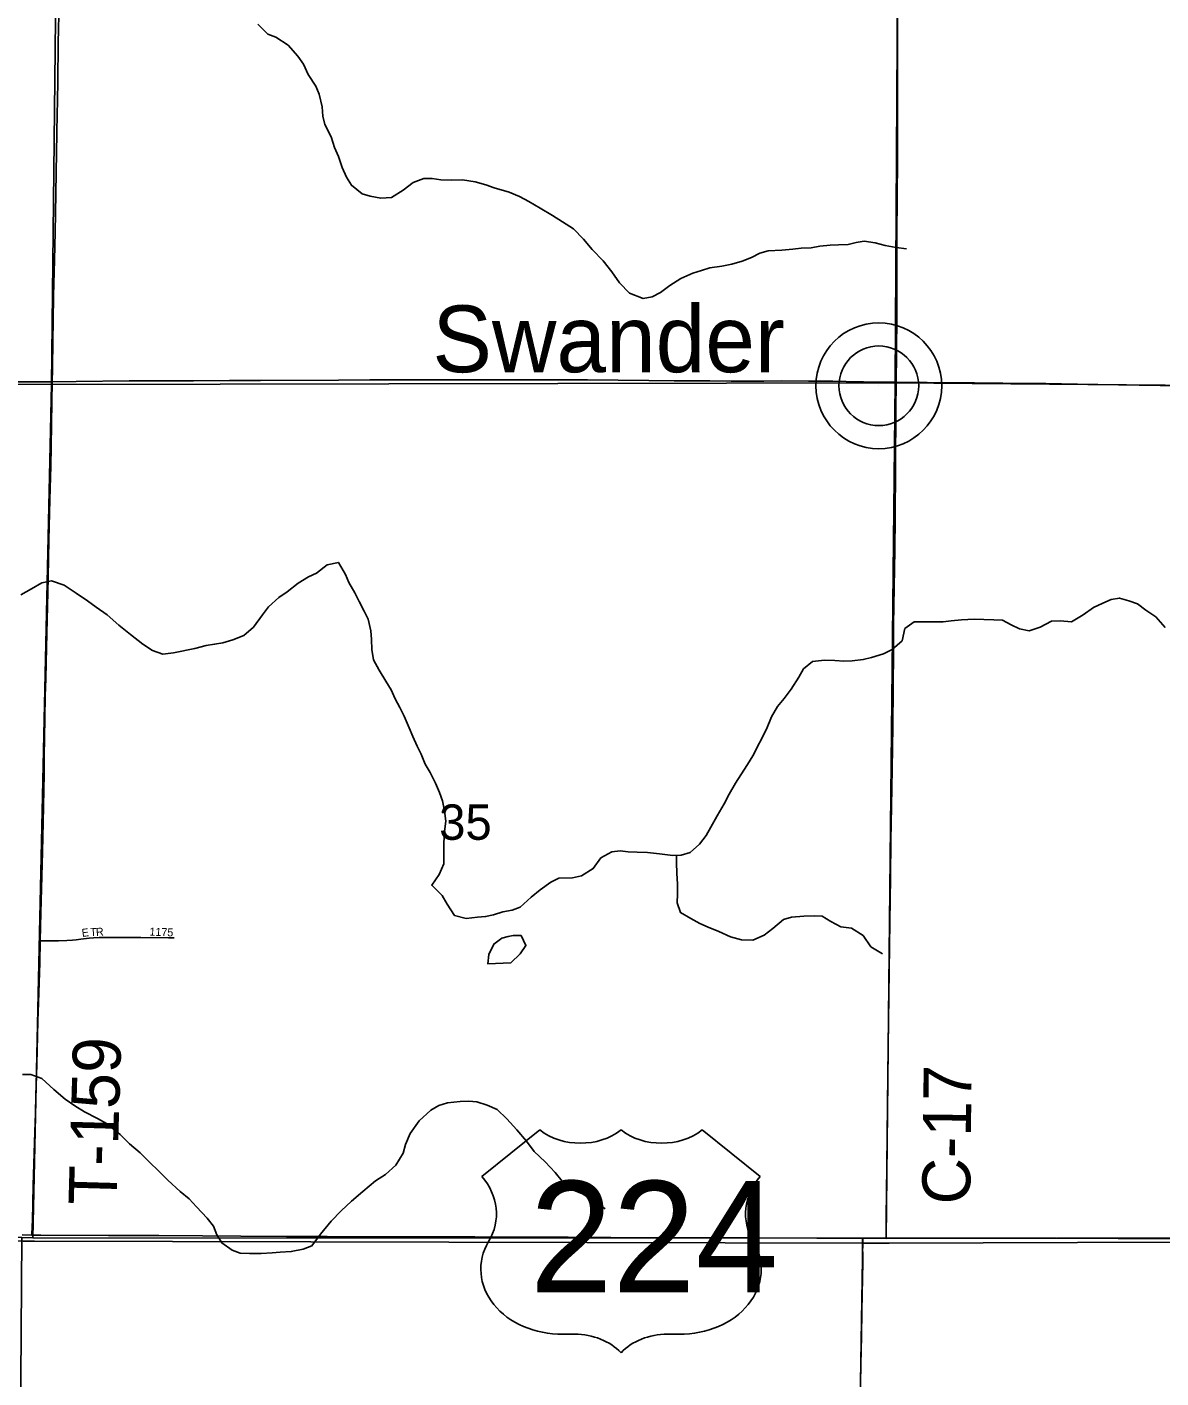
# Model space of a CAD drawing. Extents: x 0 to 34, y 0 to 22.
# Drawn here: x 7.481 to 8.152, y 17.325 to 18.124 of the extents above; entities that cross this region are included whole.
import ezdxf

# ---------------------------------------------------------------- set-up
doc = ezdxf.new("R2010")
doc.units = 0
for name, color, linetype in [('GM_X_County_Road', 7, 'Continuous'), ('GM_X_County_Road_Text', 7, 'Continuous'), ('GM_X_Minor_Lake', 7, 'Continuous'), ('GM_X_Minor_River', 7, 'Continuous'), ('GM_X_Section', 7, 'Continuous'), ('GM_X_Section_Text', 7, 'Continuous'), ('GM_X_Township', 7, 'Continuous'), ('GM_X_Township_Road', 7, 'Continuous'), ('GM_X_Township_Road_Text', 7, 'Continuous'), ('GM_X_Township_Subdivision', 7, 'Continuous'), ('GM_X_Township_Subdivision_Text', 7, 'Continuous'), ('GM_X_Unincorporated', 7, 'Continuous'), ('GM_X_Unincorporated_Location', 7, 'Continuous'), ('GM_X_Unincorporated_Text', 7, 'Continuous'), ('GM_X_US_Location', 7, 'Continuous'), ('GM_X_US_Route', 7, 'Continuous'), ('GM_X_US_Shield', 7, 'Continuous')]:
    doc.layers.add(name, color=color, linetype=linetype)

msp = doc.modelspace()

# ---------------------------------------------------------------- linework, layer by layer
at = {"layer": 'GM_X_County_Road'}
for points in [[(7.99571, 17.91394), (7.99585, 17.93046), (7.99605, 17.95429), (7.99603, 17.97419), (7.99617, 18.00589), (7.99623, 18.01863), (7.99641, 18.05025), (7.99647, 18.0754), (7.99657, 18.12233), (7.99659, 18.13787), (7.99671, 18.16117), (7.99673, 18.17267), (7.99692, 18.19444), (7.99714, 18.23162), (7.99728, 18.2571), (7.99724, 18.28784), (7.99731, 18.30959), (7.99763, 18.34688), (7.99777, 18.36771), (7.9982, 18.40065), (7.99821, 18.41029), (7.9981, 18.41846), (7.99806, 18.41977)], [(7.47422, 17.91413), (7.49131, 17.91417), (7.4964, 17.91419)], [(7.4964, 17.91419), (7.51058, 17.91426), (7.54196, 17.9146), (7.55253, 17.91465), (7.56154, 17.91469), (7.57988, 17.91475), (7.60132, 17.91498), (7.61966, 17.91494), (7.66566, 17.915), (7.68431, 17.91519), (7.71943, 17.91524), (7.73839, 17.91523), (7.76357, 17.91521), (7.78252, 17.91529), (7.79496, 17.91534), (7.81298, 17.91526), (7.84935, 17.91493), (7.86427, 17.91479), (7.8854, 17.91465), (7.89814, 17.91456), (7.9174, 17.91457), (7.92766, 17.91463), (7.94383, 17.91458), (7.95813, 17.91441), (7.96621, 17.91424), (7.97366, 17.91411), (7.97645, 17.91407), (7.98608, 17.91397), (7.99509, 17.91395), (7.99571, 17.91394)], [(7.98986, 17.40743), (7.98986, 17.40832), (7.98981, 17.42062), (7.98995, 17.43365), (7.9903, 17.4678), (7.99055, 17.48674), (7.99104, 17.52059), (7.99121, 17.53581), (7.99155, 17.56564), (7.99186, 17.59455), (7.99226, 17.62095), (7.9926, 17.643), (7.99291, 17.66288), (7.99331, 17.68493), (7.99371, 17.7104), (7.99403, 17.75515), (7.99411, 17.77038), (7.99484, 17.81452), (7.99509, 17.83409), (7.99531, 17.86298), (7.99551, 17.89904), (7.9957, 17.91239), (7.99571, 17.91394)], [(7.99571, 17.91394), (8.01405, 17.91379), (8.04202, 17.9135), (8.0588, 17.91332), (8.08429, 17.91304), (8.10294, 17.91274), (8.12718, 17.91239), (8.16416, 17.9118)]]:
    msp.add_lwpolyline(points, dxfattribs=at)
at = {"layer": 'GM_X_Minor_Lake'}
for points in [[(7.76618, 17.58588), (7.76237, 17.58503), (7.75761, 17.58144), (7.75474, 17.57538), (7.75414, 17.56969), (7.76762, 17.57039)], [(7.76762, 17.57039), (7.77315, 17.57568), (7.77659, 17.5806), (7.77376, 17.5865), (7.76902, 17.58652), (7.76618, 17.58588)]]:
    msp.add_lwpolyline(points, dxfattribs=at)
at = {"layer": 'GM_X_Minor_River'}
for points in [[(7.61793, 18.12575), (7.62398, 18.11984), (7.62871, 18.11811), (7.63591, 18.11334), (7.64176, 18.10686), (7.64497, 18.1021), (7.64779, 18.09583), (7.65232, 18.08897), (7.65438, 18.08422), (7.65606, 18.07681), (7.65642, 18.07131), (7.65773, 18.06637), (7.66149, 18.05914), (7.66336, 18.05268), (7.66581, 18.04735), (7.66787, 18.04089), (7.6705, 18.03519), (7.67352, 18.03043), (7.67976, 18.02528), (7.6845, 18.02393), (7.69076, 18.02277), (7.69702, 18.02312), (7.70406, 18.02746), (7.70996, 18.03199), (7.71624, 18.03443), (7.72117, 18.03441), (7.72629, 18.03363), (7.73256, 18.03341), (7.7392, 18.03357), (7.7466, 18.0324), (7.75285, 18.03067), (7.75778, 18.02894), (7.76669, 18.02624), (7.77275, 18.02375), (7.77843, 18.02088), (7.78506, 18.01687), (7.79244, 18.01247), (7.79831, 18.00884), (7.80475, 18.00464), (7.8108, 17.99854), (7.81589, 17.99244), (7.82232, 17.98578), (7.82742, 17.97911), (7.83194, 17.97264), (7.83799, 17.96654), (7.84595, 17.96347), (7.85127, 17.9644), (7.85621, 17.96703), (7.86173, 17.971), (7.8682, 17.97514), (7.87543, 17.97834), (7.88056, 17.98003), (7.8855, 17.98152), (7.89253, 17.98244), (7.89842, 17.98375), (7.9045, 17.98543), (7.9102, 17.98768), (7.91496, 17.99013), (7.9199, 17.99163), (7.92806, 17.99197), (7.93452, 17.99251), (7.93945, 17.99325), (7.94534, 17.99342), (7.95047, 17.99434), (7.95673, 17.99489), (7.96167, 17.99525), (7.96736, 17.99541), (7.97211, 17.99653), (7.97686, 17.99727), (7.98331, 17.99629), (7.98919, 17.99475), (7.99563, 17.99358), (8.00189, 17.9928)], [(7.65282, 17.80088), (7.6591, 17.80579), (7.66575, 17.80728), (7.66989, 17.80005), (7.67196, 17.7953), (7.67535, 17.78921), (7.67799, 17.78408), (7.681, 17.77837), (7.68326, 17.77362), (7.68494, 17.76678), (7.6853, 17.76165), (7.68546, 17.75577), (7.68639, 17.74969), (7.68978, 17.7436), (7.69373, 17.73695), (7.69694, 17.73181), (7.69919, 17.72649), (7.70202, 17.72135), (7.70465, 17.71621), (7.70747, 17.70937), (7.70973, 17.70424), (7.71236, 17.69853), (7.71462, 17.69378), (7.71706, 17.68789), (7.72008, 17.68294), (7.72309, 17.67666), (7.72553, 17.67115), (7.72722, 17.66621), (7.72852, 17.66032), (7.72926, 17.65424), (7.72847, 17.64798), (7.72806, 17.64115), (7.72801, 17.62901), (7.72533, 17.62257), (7.72094, 17.61632), (7.72717, 17.61022), (7.73, 17.60509), (7.73434, 17.59843), (7.74135, 17.59669), (7.748, 17.59742), (7.75274, 17.59778), (7.75749, 17.59871), (7.763, 17.60059), (7.76851, 17.60151), (7.77326, 17.60339), (7.77974, 17.60925), (7.78507, 17.61359), (7.79136, 17.61812), (7.79611, 17.62037), (7.80427, 17.62072), (7.80959, 17.62183), (7.81644, 17.62617), (7.82102, 17.63241), (7.82749, 17.63599), (7.83243, 17.63654), (7.83717, 17.63595), (7.84249, 17.63593), (7.84856, 17.63571), (7.85558, 17.63492), (7.86354, 17.63394), (7.86848, 17.63411), (7.8738, 17.63561), (7.87933, 17.64052), (7.88333, 17.64562), (7.88601, 17.65055), (7.88984, 17.65736), (7.89385, 17.66437), (7.89691, 17.67024), (7.90073, 17.67667), (7.90379, 17.6816), (7.9078, 17.68765), (7.91086, 17.69276), (7.9189, 17.70867), (7.92196, 17.71587), (7.92541, 17.72193), (7.92941, 17.72684), (7.93361, 17.73233), (7.9382, 17.73933), (7.94088, 17.74426), (7.94621, 17.7486), (7.95323, 17.74952), (7.95931, 17.7493), (7.96481, 17.7489), (7.96974, 17.74907), (7.9762, 17.7498), (7.98114, 17.75092), (7.98817, 17.75317), (7.99331, 17.7558), (7.99921, 17.7609), (8.00076, 17.7681), (8.00628, 17.77207), (8.0133, 17.77204), (8.01862, 17.7722), (8.02355, 17.77218), (8.0283, 17.77273), (8.03438, 17.77328), (8.04178, 17.77363), (8.04766, 17.77341), (8.05354, 17.77339), (8.05867, 17.77317), (8.06378, 17.77031)], [(7.47777, 17.78815), (7.48405, 17.79173), (7.49014, 17.79512), (7.49603, 17.79642), (7.50342, 17.79373), (7.51061, 17.78915), (7.51724, 17.78456), (7.52234, 17.78075), (7.52897, 17.77617), (7.53578, 17.77006), (7.54277, 17.76453), (7.54996, 17.75881), (7.55564, 17.75518), (7.5619, 17.75306), (7.56816, 17.7538), (7.5807, 17.7564), (7.58754, 17.75808), (7.59248, 17.75882), (7.59723, 17.75975), (7.6033, 17.76143), (7.60977, 17.76406), (7.61548, 17.76897), (7.62083, 17.77616), (7.62427, 17.78108), (7.63036, 17.78656), (7.63531, 17.78995), (7.64197, 17.79505), (7.64806, 17.79882), (7.65282, 17.80088)], [(8.06378, 17.77031), (8.0687, 17.76801), (8.07439, 17.76685), (8.08086, 17.76891), (8.08751, 17.77248), (8.09264, 17.77265), (8.09947, 17.77205), (8.10632, 17.7762), (8.11241, 17.78054), (8.11793, 17.78317), (8.12287, 17.78524), (8.12781, 17.78617), (8.1333, 17.78463), (8.13842, 17.78271), (8.14334, 17.77908), (8.1494, 17.77507), (8.15487, 17.76879)], [(7.86575, 17.63402), (7.8658, 17.62957), (7.86597, 17.62349), (7.86632, 17.61685), (7.8663, 17.61116), (7.86608, 17.60585), (7.86815, 17.60014), (7.8742, 17.59651), (7.87951, 17.59364), (7.88443, 17.59154), (7.89068, 17.58885), (7.89769, 17.58579), (7.90414, 17.58405), (7.91097, 17.58383), (7.91763, 17.58684), (7.92277, 17.59062), (7.92905, 17.59609), (7.9338, 17.5974), (7.94102, 17.59794), (7.94709, 17.5981), (7.95184, 17.59789), (7.95714, 17.59483), (7.96301, 17.59158), (7.96927, 17.5908), (7.97608, 17.5866), (7.98061, 17.57994), (7.98761, 17.57573)], [(7.47886, 17.50424), (7.48379, 17.50422), (7.49024, 17.50191), (7.49742, 17.49543), (7.50404, 17.48971), (7.50972, 17.4857), (7.5154, 17.48226), (7.52316, 17.47824), (7.52846, 17.47538), (7.5366, 17.46889), (7.54208, 17.46336), (7.54832, 17.45802), (7.55418, 17.45231), (7.55909, 17.44754), (7.56476, 17.44183), (7.57213, 17.43515), (7.57743, 17.43076), (7.58178, 17.426), (7.58801, 17.41933), (7.59179, 17.41458), (7.59385, 17.40944), (7.59668, 17.40469), (7.60292, 17.4003), (7.60766, 17.39857), (7.61316, 17.39836), (7.62, 17.39833), (7.62645, 17.39887), (7.6312, 17.39923), (7.63784, 17.39958), (7.64487, 17.40088), (7.65, 17.40294), (7.65516, 17.40994), (7.66145, 17.41751), (7.66736, 17.42356), (7.67346, 17.42941), (7.68013, 17.43508), (7.68774, 17.44131), (7.69364, 17.44508), (7.69974, 17.45075), (7.70395, 17.45775), (7.70548, 17.46287), (7.70817, 17.4695), (7.71352, 17.47687), (7.72038, 17.4833), (7.72513, 17.48594), (7.73026, 17.48762), (7.73767, 17.48835)], [(7.73767, 17.48835), (7.74279, 17.48852), (7.74754, 17.48812), (7.75379, 17.48619), (7.75966, 17.4837), (7.76533, 17.47799), (7.77119, 17.47151), (7.77704, 17.46484), (7.78157, 17.45875), (7.788, 17.45265), (7.79386, 17.44636), (7.79801, 17.44122), (7.80387, 17.43626), (7.81013, 17.43377), (7.8177, 17.42919), (7.82356, 17.4248)]]:
    msp.add_lwpolyline(points, dxfattribs=at)
at = {"layer": 'GM_X_Section'}
for points in [[(6.99984, 18.41775), (7.50153, 18.41698), (7.49596, 17.91244), (6.98884, 17.91553)], [(7.50153, 18.41698), (7.99816, 18.41923), (7.99504, 17.91354), (7.49596, 17.91244)], [(7.99816, 18.41923), (8.49985, 18.41215), (8.49941, 18.40211), (8.49694, 17.90911), (7.99504, 17.91354)], [(6.98884, 17.91553), (7.49596, 17.91244), (7.4849, 17.40776), (7.47845, 17.4078), (6.97935, 17.41426)], [(7.49596, 17.91244), (7.99504, 17.91354), (7.98984, 17.40729), (7.97601, 17.40757), (7.4849, 17.40776)], [(7.99504, 17.91354), (8.49694, 17.90911), (8.49688, 17.89945), (8.49384, 17.40835), (7.98984, 17.40729)], [(7.47845, 17.4078), (7.4849, 17.40776), (7.97601, 17.40757), (7.9678, 16.90665), (7.47479, 16.90534)], [(7.98984, 17.40729), (8.49384, 17.40835), (8.48909, 16.91461), (7.9678, 16.90665), (7.97601, 17.40757)]]:
    msp.add_lwpolyline(points, close=True, dxfattribs=at)
at = {"layer": 'GM_X_Township'}
for points in [[(6.78218, 20.41492), (7.02348, 20.4144), (7.09974, 20.41612), (7.18499, 20.41333), (7.20165, 20.41351), (7.32949, 20.41334), (7.74573, 20.4181), (7.8262, 20.42148), (7.97527, 20.42654), (8.50107, 20.45272), (8.493, 20.16746), (8.48607, 19.91593), (8.486, 19.91208), (8.49318, 19.41213), (8.49927, 18.91004), (8.49985, 18.40187), (8.49713, 17.90434), (8.4927, 17.4064), (7.9915, 17.4046), (7.97617, 17.40455), (7.48595, 17.40578), (7.4791, 17.40579), (6.97838, 17.41123), (6.85112, 17.41144)], [(5.45812, 16.85635), (5.46352, 17.41199), (5.85482, 17.41232), (6.21985, 17.41235), (6.41604, 17.41268), (6.74587, 17.41079), (6.85112, 17.41144), (6.97838, 17.41123), (7.4791, 17.40579), (7.48595, 17.40578), (7.97617, 17.40455), (7.9915, 17.4046), (8.4927, 17.4064), (8.48897, 16.91291)]]:
    msp.add_lwpolyline(points, dxfattribs=at)
at = {"layer": 'GM_X_Township_Road'}
for points in [[(7.4964, 17.91419), (7.49652, 17.92177), (7.49674, 17.93886), (7.49686, 17.94973), (7.4972, 17.96526), (7.49768, 17.98608), (7.49805, 18.00286), (7.49822, 18.01374), (7.49894, 18.04978), (7.49912, 18.06096), (7.49933, 18.07277), (7.49946, 18.07992), (7.49968, 18.09265), (7.49993, 18.11344), (7.50016, 18.12399), (7.50033, 18.12988)], [(7.48926, 17.58342), (7.48971, 17.59991), (7.49057, 17.63595), (7.49097, 17.65335), (7.49119, 17.66298), (7.49157, 17.68224), (7.49169, 17.69281), (7.49184, 17.70337), (7.49202, 17.71517), (7.49229, 17.72822), (7.49253, 17.73847), (7.49274, 17.74779), (7.49315, 17.7655), (7.4935, 17.78134), (7.49393, 17.79843), (7.49416, 17.80931), (7.49445, 17.82048), (7.495, 17.84441), (7.49552, 17.86428), (7.49568, 17.87578), (7.496, 17.88883), (7.49622, 17.9025), (7.4964, 17.91419)], [(7.48432, 17.40933), (7.48451, 17.41474), (7.48463, 17.41785), (7.48491, 17.4281), (7.48519, 17.43866), (7.48616, 17.47033), (7.48645, 17.48119), (7.48673, 17.49237), (7.48709, 17.50323), (7.48746, 17.51845), (7.48791, 17.53614), (7.4883, 17.54669), (7.48898, 17.5706), (7.48926, 17.58342)], [(7.97444, 17.30974), (7.97488, 17.3329), (7.97511, 17.34925), (7.9754, 17.36444), (7.97594, 17.39327), (7.97586, 17.40597), (7.97585, 17.40747)]]:
    msp.add_lwpolyline(points, dxfattribs=at)
at = {"layer": 'GM_X_Township_Subdivision'}
msp.add_lwpolyline([(7.48926, 17.58342), (7.49362, 17.58349), (7.50013, 17.58349), (7.50499, 17.5836), (7.50839, 17.58381), (7.51056, 17.584), (7.51334, 17.58432), (7.51827, 17.58495), (7.52075, 17.58518), (7.52416, 17.58535), (7.53006, 17.58546), (7.54871, 17.58532), (7.56519, 17.58513), (7.56848, 17.58509)], dxfattribs=at)
at = {"layer": 'GM_X_Unincorporated'}
for radius in [0.0372, 0.02358]:
    msp.add_circle((7.98543, 17.91176), radius, dxfattribs=at)
at = {"layer": 'GM_X_Unincorporated_Location'}
msp.add_line((7.98543, 17.91176), (7.98543, 17.91176), dxfattribs=at)
at = {"layer": 'GM_X_US_Route'}
msp.add_lwpolyline([(7.47861, 17.40939), (7.48432, 17.40933), (7.48961, 17.40928), (7.5297, 17.40904), (7.55955, 17.40902), (7.58534, 17.40883), (7.60803, 17.4087), (7.63507, 17.40847), (7.659, 17.40846), (7.74634, 17.40826), (7.77152, 17.40812), (7.80166, 17.40798), (7.85232, 17.40774), (7.91107, 17.40765), (7.94868, 17.40753), (7.97585, 17.40747), (7.98986, 17.40743), (7.99902, 17.40742), (8.02762, 17.40744), (8.0618, 17.40744), (8.09009, 17.40743), (8.12707, 17.40726), (8.17121, 17.40737)], dxfattribs=at)
at = {"layer": 'GM_X_US_Shield'}
for p, q in [((7.78484, 17.47151), (7.7505, 17.44405)), ((7.9153, 17.44405), (7.88097, 17.47151)), ((7.79857, 17.35066), (7.80544, 17.35066)), ((7.86037, 17.35066), (7.86723, 17.35066))]:
    msp.add_line(p, q, dxfattribs=at)
for centre, major_axis, start_param, end_param in [((7.80887, 17.49113), (-0.03433, 0), 0.795399, 2.346194), ((7.85694, 17.49113), (-0.03433, 0), 0.795399, 2.346194), ((7.71113, 17.42199), (0.04807, 0), 5.838949, 6.894067), ((7.95467, 17.42199), (-0.04807, 0), 5.672304, 6.727422), ((7.79803, 17.38911), (0.04807, 0), 2.702327, 4.723529), ((7.86777, 17.38911), (-0.04807, 0), 1.559657, 3.580859), ((7.80544, 17.3232), (-0.03433, 0), 3.785094, 4.712389), ((7.86037, 17.3232), (-0.03433, 0), 4.712389, 5.639684)]:
    msp.add_ellipse(centre, major_axis=major_axis, ratio=0.8, start_param=start_param, end_param=end_param, dxfattribs=at)

# ---------------------------------------------------------------- texts
at = {"layer": 'GM_X_County_Road_Text'}
msp.add_text('C-17', height=0.028409, rotation=89.32567, dxfattribs=at).set_placement((8.03943, 17.42733))
at = {"layer": 'GM_X_Section_Text'}
msp.add_text('35', height=0.020928, rotation=0.00001, dxfattribs=at).set_placement((7.72528, 17.64316))
at = {"layer": 'GM_X_Township_Road_Text'}
msp.add_text('T-159', height=0.028409, rotation=88.3486, dxfattribs=at).set_placement((7.53436, 17.42675))
at = {"layer": 'GM_X_Township_Subdivision_Text'}
for s, height, rotation, p in [('E', 0.00473, 7.12165, (7.51413, 17.58567)), ('T', 0.00473, 2.10391, (7.51887, 17.5861)), ('R', 0.00473, 4.1389, (7.52238, 17.58623)), ('1175', 0.004735, 357.8798, (7.55386, 17.58651))]:
    msp.add_text(s, height=height, rotation=rotation, dxfattribs=at).set_placement(p)
at = {"layer": 'GM_X_Unincorporated_Text'}
msp.add_text('Swander', height=0.039489, rotation=0.00001, dxfattribs=at).set_placement((7.72132, 17.91978))
at = {"layer": 'GM_X_US_Location'}
for s in ['0', '/']:
    msp.add_text(s, height=0.0000947, dxfattribs=at).set_placement((7.83296, 17.40829))
msp.add_text('224', height=0.0000947, rotation=0.00001, dxfattribs=at).set_placement((7.80382, 17.38869))
at = {"layer": 'GM_X_US_Shield'}
msp.add_text('224', height=0.065918, dxfattribs=at).set_placement((7.7789, 17.37538))

doc.saveas('drawing.dxf')
